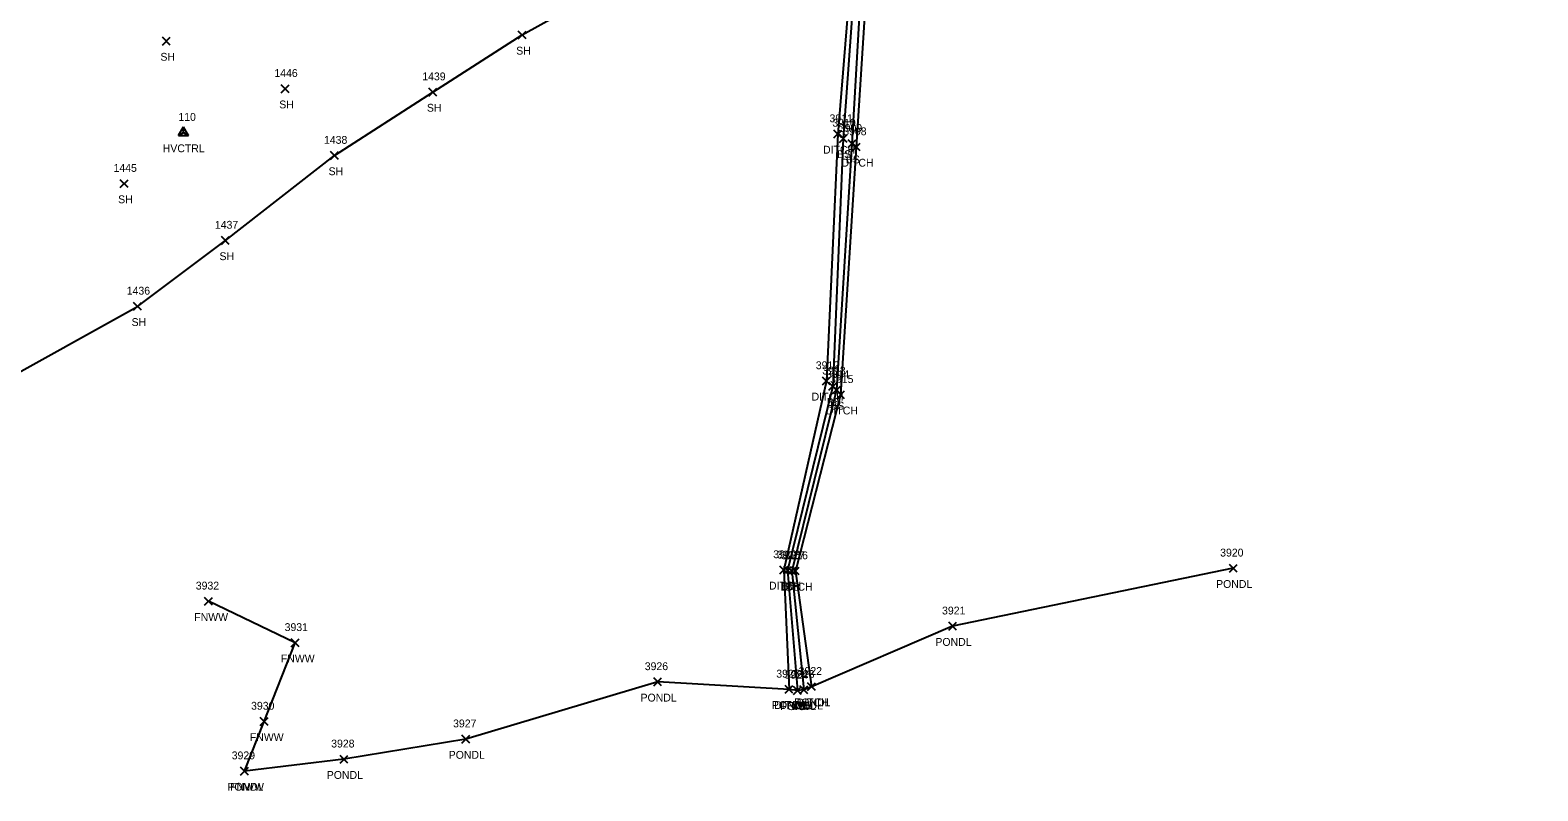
# Model space of a CAD drawing. Extents: x 1599569 to 1610055, y 642560 to 647860.
# Drawn here: x 1602263.8 to 1602648.3, y 647075.7 to 647269.5 of the extents above; entities that cross this region are included whole.
import ezdxf

# ---------------------------------------------------------------- set-up
doc = ezdxf.new("R2010")
doc.units = 0
for name, color, linetype in [('C_A', 7, 'Continuous'), ('C_I', 7, 'Continuous'), ('CPSM', 7, 'Continuous'), ('D_A', 7, 'Continuous'), ('D_I', 7, 'Continuous'), ('D_TIC', 7, 'Continuous'), ('DD', 7, 'Continuous'), ('L_A', 7, 'Continuous'), ('L_I', 7, 'Continuous'), ('L_TIC', 7, 'Continuous'), ('LAWE', 7, 'Continuous'), ('LELB', 7, 'Continuous'), ('LFNC', 7, 'Continuous'), ('LSOGP', 7, 'Continuous')]:
    doc.layers.add(name, color=color, linetype=linetype)

msp = doc.modelspace()

# ---------------------------------------------------------------- linework, layer by layer
at = {"layer": 'CPSM'}
for p, q in [((1602301.7, 647242.68), (1602302.95, 647244.85)), ((1602304.2, 647242.68), (1602302.95, 647244.85)), ((1602302.96, 647243.4), (1602302.95, 647244.85)), ((1602301.7, 647242.68), (1602302.96, 647243.4)), ((1602301.7, 647242.68), (1602304.2, 647242.68)), ((1602302.96, 647243.4), (1602302.96, 647243.4)), ((1602302.96, 647243.4), (1602304.2, 647242.68))]:
    msp.add_line(p, q, dxfattribs=at)
at = {"layer": 'D_TIC'}
for points in [[(1602468.83, 647242.04), (1602470.83, 647244.04)], [(1602470.83, 647242.04), (1602468.83, 647244.04)], [(1602473.53, 647238.73), (1602475.53, 647240.73)], [(1602475.53, 647238.73), (1602473.53, 647240.73)], [(1602465.89, 647179.12), (1602467.89, 647181.12)], [(1602467.89, 647179.12), (1602465.89, 647181.12)], [(1602469.54, 647175.59), (1602471.54, 647177.59)], [(1602471.54, 647175.59), (1602469.54, 647177.59)], [(1602455.04, 647130.96), (1602457.04, 647132.96)], [(1602457.04, 647130.96), (1602455.04, 647132.96)], [(1602457.99, 647130.68), (1602459.99, 647132.68)], [(1602459.99, 647130.68), (1602457.99, 647132.68)], [(1602456.38, 647100.53), (1602458.38, 647102.53)], [(1602458.38, 647100.53), (1602456.38, 647102.53)], [(1602462.1, 647101.21), (1602464.1, 647103.21)], [(1602464.1, 647101.21), (1602462.1, 647103.21)]]:
    msp.add_lwpolyline(points, dxfattribs=at)
at = {"layer": 'DD'}
for points in [[(1602480.64, 647337.67), (1602475.41, 647311.85), (1602469.83, 647243.04), (1602466.89, 647180.12), (1602456.04, 647131.96), (1602457.38, 647101.53)], [(1602484.49, 647338.04), (1602479.04, 647310.08), (1602474.53, 647239.73), (1602470.54, 647176.59), (1602458.99, 647131.68), (1602463.1, 647102.21)]]:
    msp.add_lwpolyline(points, dxfattribs=at)
at = {"layer": 'L_TIC'}
for points in [[(1602297.57, 647265.72), (1602299.57, 647267.72)], [(1602299.57, 647265.72), (1602297.57, 647267.72)], [(1602388.31, 647267.28), (1602390.31, 647269.28)], [(1602390.31, 647267.28), (1602388.31, 647269.28)], [(1602327.87, 647253.58), (1602329.87, 647255.58)], [(1602329.87, 647253.58), (1602327.87, 647255.58)], [(1602365.54, 647252.73), (1602367.54, 647254.73)], [(1602367.54, 647252.73), (1602365.54, 647254.73)], [(1602470.21, 647240.91), (1602472.21, 647242.91)], [(1602472.21, 647240.91), (1602470.21, 647242.91)], [(1602472.43, 647239.57), (1602474.43, 647241.57)], [(1602474.43, 647239.57), (1602472.43, 647241.57)], [(1602340.47, 647236.55), (1602342.47, 647238.55)], [(1602342.47, 647236.55), (1602340.47, 647238.55)], [(1602286.79, 647229.4), (1602288.79, 647231.4)], [(1602288.79, 647229.4), (1602286.79, 647231.4)], [(1602312.63, 647214.91), (1602314.63, 647216.91)], [(1602314.63, 647214.91), (1602312.63, 647216.91)], [(1602290.22, 647198.12), (1602292.22, 647200.12)], [(1602292.22, 647198.12), (1602290.22, 647200.12)], [(1602467.55, 647177.76), (1602469.55, 647179.76)], [(1602469.55, 647177.76), (1602467.55, 647179.76)], [(1602468.46, 647176.82), (1602470.46, 647178.82)], [(1602470.46, 647176.82), (1602468.46, 647178.82)], [(1602569.68, 647131.38), (1602571.68, 647133.38)], [(1602571.68, 647131.38), (1602569.68, 647133.38)], [(1602456.01, 647130.86), (1602458.01, 647132.86)], [(1602458.01, 647130.86), (1602456.01, 647132.86)], [(1602457.07, 647130.68), (1602459.07, 647132.68)], [(1602459.07, 647130.68), (1602457.07, 647132.68)], [(1602308.34, 647122.97), (1602310.34, 647124.97)], [(1602310.34, 647122.97), (1602308.34, 647124.97)], [(1602498.09, 647116.62), (1602500.09, 647118.62)], [(1602500.09, 647116.62), (1602498.09, 647118.62)], [(1602330.43, 647112.39), (1602332.43, 647114.39)], [(1602332.43, 647112.39), (1602330.43, 647114.39)], [(1602422.89, 647102.43), (1602424.89, 647104.43)], [(1602424.89, 647102.43), (1602422.89, 647104.43)], [(1602456.38, 647100.53), (1602458.38, 647102.53)], [(1602458.38, 647100.53), (1602456.38, 647102.53)], [(1602460.17, 647100.43), (1602462.17, 647102.43)], [(1602462.17, 647100.43), (1602460.17, 647102.43)], [(1602460.17, 647100.43), (1602462.17, 647102.43)], [(1602462.17, 647100.43), (1602460.17, 647102.43)], [(1602462.1, 647101.21), (1602464.1, 647103.21)], [(1602464.1, 647101.21), (1602462.1, 647103.21)], [(1602458.52, 647100.25), (1602460.52, 647102.25)], [(1602460.52, 647100.25), (1602458.52, 647102.25)], [(1602458.52, 647100.25), (1602460.52, 647102.25)], [(1602460.52, 647100.25), (1602458.52, 647102.25)], [(1602322.52, 647092.35), (1602324.52, 647094.35)], [(1602324.52, 647092.35), (1602322.52, 647094.35)], [(1602373.96, 647087.85), (1602375.96, 647089.85)], [(1602375.96, 647087.85), (1602373.96, 647089.85)], [(1602342.87, 647082.72), (1602344.87, 647084.72)], [(1602344.87, 647082.72), (1602342.87, 647084.72)], [(1602317.51, 647079.71), (1602319.51, 647081.71)], [(1602319.51, 647079.71), (1602317.51, 647081.71)], [(1602317.51, 647079.71), (1602319.51, 647081.71)], [(1602319.51, 647079.71), (1602317.51, 647081.71)]]:
    msp.add_lwpolyline(points, dxfattribs=at)
at = {"layer": 'LAWE'}
msp.add_lwpolyline([(1602570.68, 647132.38), (1602499.09, 647117.62), (1602463.1, 647102.21), (1602461.17, 647101.43), (1602459.52, 647101.25), (1602457.38, 647101.53), (1602423.89, 647103.43), (1602374.96, 647088.85), (1602343.87, 647083.72), (1602318.51, 647080.71)], dxfattribs=at)
at = {"layer": 'LELB'}
for points in [[(1602481.57, 647337.19), (1602476.21, 647311.4), (1602471.21, 647241.91), (1602468.55, 647178.76), (1602457.01, 647131.86), (1602459.52, 647101.25)], [(1602483.35, 647336.67), (1602477.48, 647311.14), (1602473.43, 647240.57), (1602469.46, 647177.82), (1602458.07, 647131.68), (1602461.17, 647101.43)]]:
    msp.add_lwpolyline(points, dxfattribs=at)
at = {"layer": 'LFNC'}
msp.add_lwpolyline([(1602318.51, 647080.71), (1602323.52, 647093.35), (1602331.43, 647113.39), (1602309.34, 647123.97)], dxfattribs=at)
at = {"layer": 'LSOGP'}
msp.add_lwpolyline([(1602254.53, 647178.83), (1602291.22, 647199.13), (1602313.63, 647215.92), (1602341.47, 647237.55), (1602366.54, 647253.73), (1602389.31, 647268.29), (1602449.83, 647301.87), (1602453.66, 647307.87), (1602460.55, 647316.67), (1602462.33, 647322.8), (1602472.93, 647343.79), (1602485.85, 647364.3), (1602486.56, 647364.52), (1602487.54, 647364.39), (1602501.5, 647362.17), (1602506.13, 647378.88), (1602530.31, 647430.66), (1602560.99, 647425.29), (1602596.7, 647426.6), (1602638.54, 647420.26), (1602674.58, 647411.62)], dxfattribs=at)

# ---------------------------------------------------------------- texts
at = {"layer": 'C_A'}
msp.add_text('HVCTRL', height=2, dxfattribs=at).set_placement((1602297.65, 647238.4))
at = {"layer": 'C_I'}
msp.add_text('110', height=2, dxfattribs=at).set_placement((1602301.64, 647246.4))
at = {"layer": 'D_A'}
for p in [(1602466.06, 647238.04), (1602470.76, 647234.73), (1602463.13, 647175.12), (1602466.78, 647171.59), (1602452.27, 647126.96), (1602455.23, 647126.68), (1602453.61, 647096.53), (1602459.34, 647097.21)]:
    msp.add_text('DITCH', height=2, dxfattribs=at).set_placement(p)
at = {"layer": 'D_I'}
for s, p in [('3911', (1602467.7, 647246.04)), ('3908', (1602471.19, 647242.73)), ('3912', (1602464.2, 647183.12)), ('3915', (1602467.85, 647179.59)), ('3919', (1602453.34, 647134.96)), ('3916', (1602456.24, 647134.68)), ('3925', (1602454.12, 647104.53)), ('3922', (1602459.84, 647105.21))]:
    msp.add_text(s, height=2, dxfattribs=at).set_placement(p)
at = {"layer": 'L_A'}
for s, p in [('SH', (1602387.8, 647263.28)), ('SH', (1602297.06, 647261.72)), ('SH', (1602327.36, 647249.58)), ('SH', (1602365.03, 647248.73)), ('BS', (1602469.65, 647236.91)), ('BS', (1602471.87, 647235.57)), ('SH', (1602339.95, 647232.55)), ('SH', (1602286.28, 647225.4)), ('SH', (1602312.12, 647210.91)), ('SH', (1602289.71, 647194.12)), ('BS', (1602466.99, 647173.76)), ('BS', (1602467.9, 647172.82)), ('PONDL', (1602566.3, 647127.38)), ('BS', (1602455.45, 647126.86)), ('BS', (1602456.51, 647126.68)), ('FNWW', (1602305.69, 647118.97)), ('PONDL', (1602494.71, 647112.62)), ('FNWW', (1602327.78, 647108.39)), ('PONDL', (1602419.51, 647098.43)), ('PONDL', (1602453, 647096.53)), ('PONDL', (1602456.79, 647096.43)), ('PONDL', (1602458.72, 647097.21)), ('BS', (1602459.61, 647096.43)), ('PONDL', (1602455.14, 647096.25)), ('BS', (1602457.96, 647096.25)), ('FNWW', (1602319.87, 647088.35)), ('PONDL', (1602370.58, 647083.85)), ('PONDL', (1602339.49, 647078.72)), ('PONDL', (1602314.13, 647075.71)), ('FNWW', (1602314.85, 647075.71))]:
    msp.add_text(s, height=2, dxfattribs=at).set_placement(p)
at = {"layer": 'L_I'}
for s, p in [('1446', (1602326.12, 647257.58)), ('1439', (1602363.84, 647256.73)), ('3910', (1602468.43, 647244.91)), ('3909', (1602470.08, 647243.57)), ('1438', (1602338.77, 647240.55)), ('1445', (1602285.1, 647233.4)), ('1437', (1602310.94, 647218.91)), ('1436', (1602288.47, 647202.12)), ('3913', (1602465.86, 647181.76)), ('3914', (1602466.77, 647180.82)), ('3920', (1602567.33, 647135.38)), ('3918', (1602454.31, 647134.86)), ('3917', (1602455.37, 647134.68)), ('3932', (1602306.08, 647126.97)), ('3921', (1602496.4, 647120.62)), ('3931', (1602328.74, 647116.39)), ('3926', (1602420.58, 647106.43)), ('3925', (1602454.12, 647104.53)), ('3924', (1602456.26, 647104.25)), ('3924', (1602456.26, 647104.25)), ('3923', (1602457.91, 647104.43)), ('3923', (1602457.91, 647104.43)), ('3922', (1602459.84, 647105.21)), ('3930', (1602320.18, 647096.35)), ('3927', (1602371.7, 647091.85)), ('3928', (1602340.61, 647086.72)), ('3929', (1602315.24, 647083.71)), ('3929', (1602315.24, 647083.71))]:
    msp.add_text(s, height=2, dxfattribs=at).set_placement(p)

doc.saveas('drawing.dxf')
